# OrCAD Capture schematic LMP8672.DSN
size A; title: LMP8671: Dual, 40V Low Noise Precision Amplifiers; rev: 1.0; note: Datasheet: July 29, 2011; note: Reference
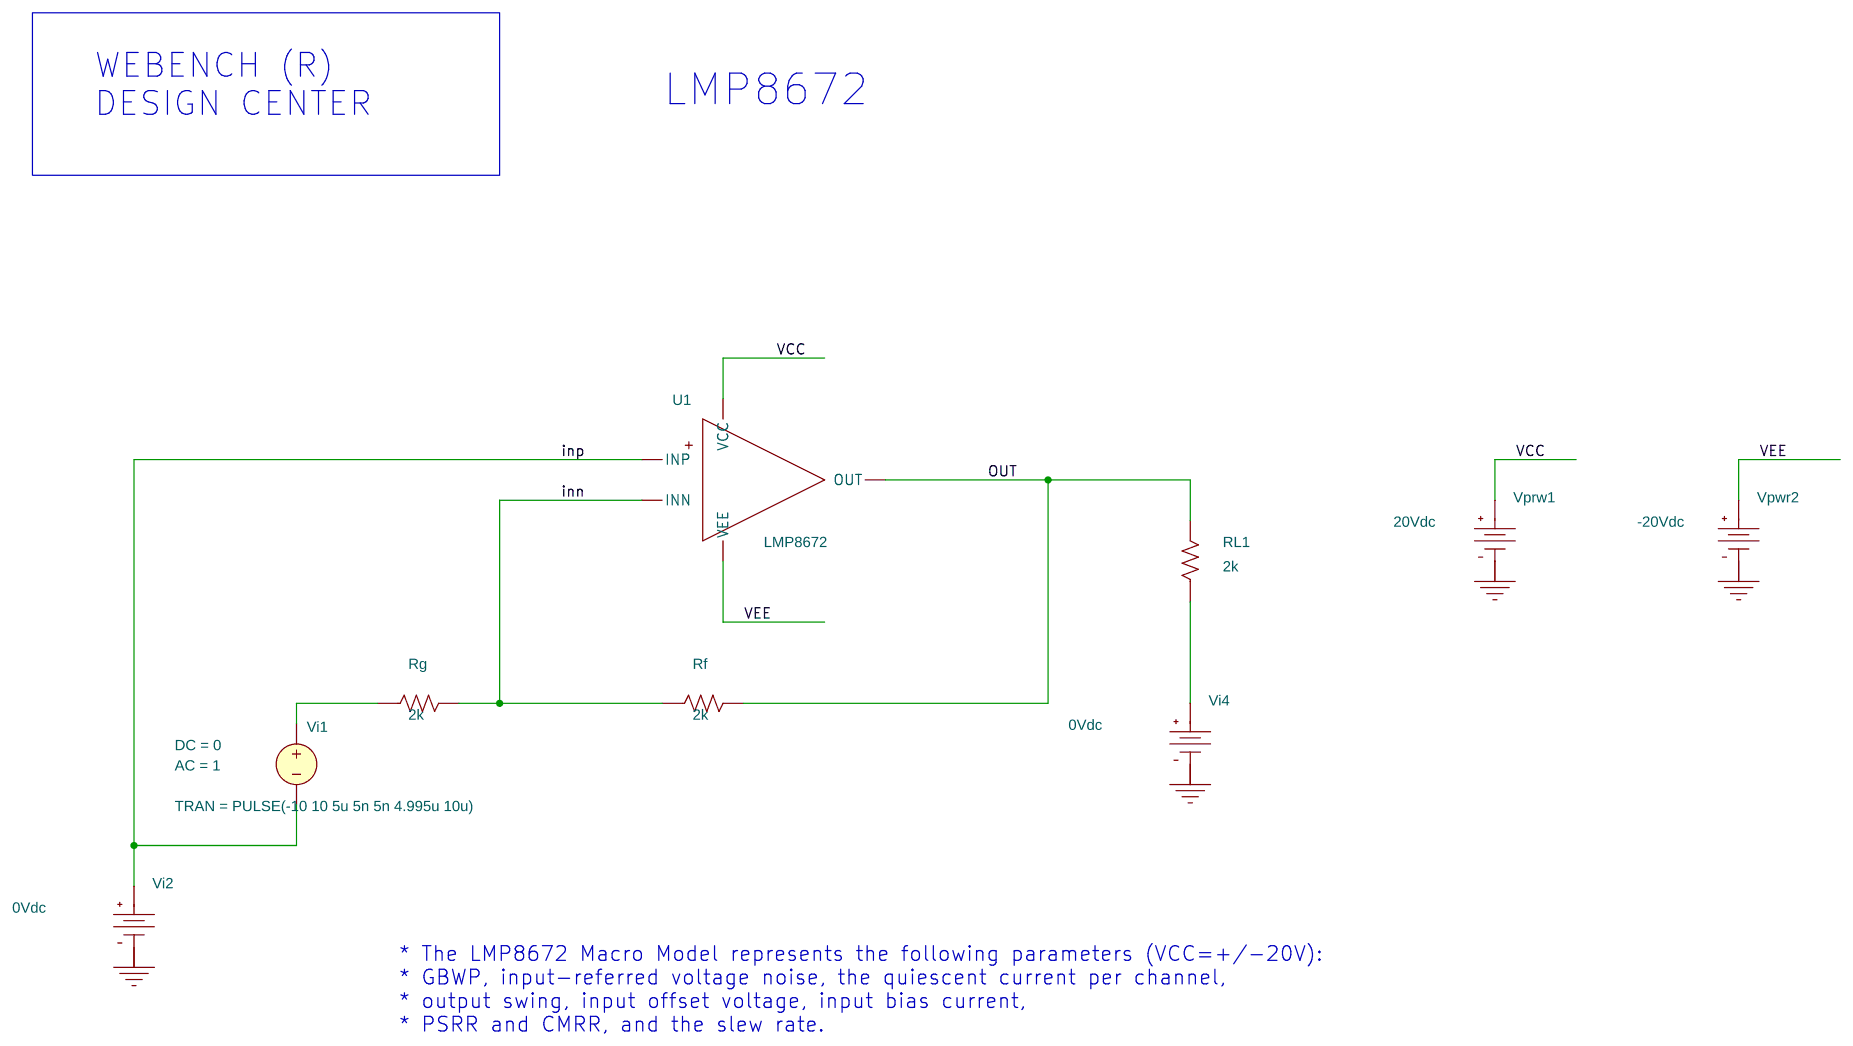
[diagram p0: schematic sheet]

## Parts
Rf  2k  [AX/RC05]
Rg  2k  [AX/RC05]
RL1  2k  [AX/RC05]
U1  LMP8672
Vi1  VSRC
Vi2  VDC
Vi4  VDC
Vprw1  VDC
Vpwr2  VDC

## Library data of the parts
Rf Rg RL1 = R
U1 = LMP8672
Vi1 = VSRC: AC: 1; DC: 0; TRAN: PULSE(-10 10 5u 5n 5n 4.995u 10u)
Vi2 Vi4 = VDC: DC: 0Vdc
Vprw1 = VDC: DC: 20Vdc
Vpwr2 = VDC: DC: -20Vdc

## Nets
VCC: U1.VCC Vprw1.0(+)
VEE: U1.VEE Vpwr2.0(+)
0: Vi2.1(-) Vi4.1(-) Vprw1.1(-) Vpwr2.1(-)
inn: Rf.1 Rg.2 U1.INN
inp: U1.INP Vi1.1(-) Vi2.0(+)
OUT: Rf.2 RL1.2 U1.OUT
N14338356: Rg.1 Vi1.0(+)
N14338414: RL1.1 Vi4.0(+)

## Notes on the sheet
- WEBENCH (R)
  DESIGN CENTER
- LMP8672
- * The LMP8672 Macro Model represents the following parameters (VCC=+/-20V):
  * GBWP, input-referred voltage noise, the quiescent current per channel,
  * output swing, input offset voltage, input bias current,
  * PSRR and CMRR, and the slew rate.
